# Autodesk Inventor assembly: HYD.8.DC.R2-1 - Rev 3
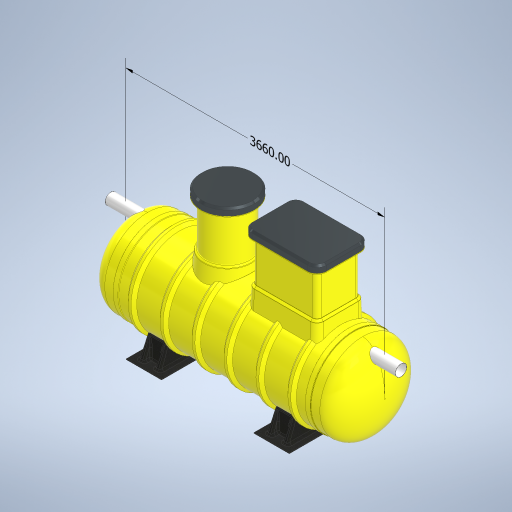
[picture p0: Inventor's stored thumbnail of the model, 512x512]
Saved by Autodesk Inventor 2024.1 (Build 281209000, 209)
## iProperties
Created: 2023-10
Part Number: HYD.8.DC.R2-1 - Rev 3
Document SubType Name: Assembly
Designer: macga
Author: macga
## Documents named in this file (43)
- D:\$ Protector Vault\Workspace\Automation Files\1. Protector Stardard Products\HydroProtectors\FAMILY\HYD.8 -Vernon\HYD.8.DC.R2-1 - Rev 3.iam
- D:\$ Protector Vault\Workspace\1. Protector Stardard Products\HydroProtectors\FAMILY\HORIZONTAL TANK - IPART\HORIZONTAL TANK - IPART.ipt
- D:\$ Protector Vault\Workspace\1. Protector Stardard Products\HydroProtectors\FAMILY\DOME - IPART\DOME - IPART.ipt
- D:\$ Protector Vault\Workspace\1. Protector Stardard Products\HydroProtectors\FAMILY\ACDTUBE - IPART\ACDTUBE - IPART.ipt
- D:\$ Protector Vault\Workspace\1. Protector Stardard Products\HydroProtectors\FAMILY\ACD FLOAT VALVE - IPART\ACD.FloatValve - IASSY\ACD.FVALVE.225.ASSY.iam
- D:\$ Protector Vault\Workspace\1. Protector Stardard Products\HydroProtectors\FAMILY\ACD FLOAT VALVE - IPART\ACD.FloatValve - IASSY.iam
- D:\$ Protector Vault\Workspace\1. Protector Stardard Products\HydroProtectors\FAMILY\ACDTUBE - IPART\ACDTUBE - IPART\ACDTUBE.225-1680.ipt
- D:\$ Protector Vault\Workspace\1. Protector Stardard Products\HydroProtectors\FAMILY\SU.600Dia Manway Adaptor - IPART\SU.MWA.HS.6R - IPART.ipt
- D:\$ Protector Vault\Workspace\1. Protector Stardard Products\HydroProtectors\FAMILY\600x900mm Manway Adaptor - IPART\600x900mm Manway Adaptor - IPART.ipt
- D:\$ Protector Vault\Workspace\1. Protector Stardard Products\HydroProtectors\Coalescer Guide Rail.ipt
- D:\$ Protector Vault\Workspace\1. Protector Stardard Products\Standard Components\600mm Riser.ipt
- D:\$ Protector Vault\Workspace\1. Protector Stardard Products\Standard Components\600x900 - 600mm Manway Riser.ipt
- D:\$ Protector Vault\Workspace\1. Protector Stardard Products\Standard Components\Flanged Vent.ipt
- D:\$ Protector Vault\Workspace\1. Protector Stardard Products\HydroProtectors\Upper Guide Rai Braket.ipt
- D:\$ Protector Vault\Workspace\1. Protector Stardard Products\Xtremeprotector\Vault\Lifting Eye.ipt
- D:\$ Protector Vault\Workspace\1. Protector Stardard Products\Xtremeprotector\Vault\Chain.ipt
- D:\$ Protector Vault\Workspace\1. Protector Stardard Products\Standard Components\600mm Cast Iron Cover ST\600mm Cass D Cover-01.ipt
- D:\$ Protector Vault\Workspace\1. Protector Stardard Products\Standard Components\600mm Cast Iron Cover ST.ipt
- D:\$ Protector Vault\Workspace\Automation Files\600x900mm Manway Cover ST B and D\600x900mm Manway Cover-D.ipt
- D:\$ Protector Vault\Workspace\Automation Files\600x900mm Manway Cover ST B and D.ipt
- D:\$ Protector Vault\Workspace\1. Protector Stardard Products\HydroProtectors\FAMILY\OUTLET ELBOW - IPART\OUTLET ELBOW - IPART.ipt
- D:\$ Protector Vault\Workspace\1. Protector Stardard Products\HydroProtectors\FAMILY\INLET PIPE ELBOW- IPART\INLET PIPE ELBOW- IPART.ipt
- D:\$ Protector Vault\Workspace\1. Protector Stardard Products\HydroProtectors\HYD Oil Probe\Oil Probe Assembly.iam
- D:\$ Protector Vault\Workspace\1. Protector Stardard Products\HydroProtectors\FAMILY\FOOT - IPART\FRP Foot - IPART.ipt
- D:\$ Protector Vault\Workspace\1. Protector Stardard Products\HydroProtectors\FAMILY\HYD.BAFFLE - IPART\SU.BAFFLE.1200\SU.BAFFLE.1200.ipt
- D:\$ Protector Vault\Workspace\1. Protector Stardard Products\HydroProtectors\FAMILY\HYD.BAFFLE - IPART\SU.BAFFLE.1200.ipt
- D:\$ Protector Vault\Workspace\1. Protector Stardard Products\HydroProtectors\FAMILY\ACD Base - IPART\SU.ACDBASE.1200\SU.ACDBASE.1200.ipt
- D:\$ Protector Vault\Workspace\1. Protector Stardard Products\HydroProtectors\FAMILY\ACD Base - IPART\SU.ACDBASE.1200.ipt
- D:\$ Protector Vault\Workspace\1. Protector Stardard Products\HydroProtectors\FAMILY\CF.BASE - IPART\CF BASE SINGLE - IPART\SU.CFBASE.1200\SU.CFBASE.1200.ipt
- D:\$ Protector Vault\Workspace\1. Protector Stardard Products\HydroProtectors\FAMILY\CF.BASE - IPART\CF BASE SINGLE - IPART\SU.CFBASE.1200.ipt
- D:\$ Protector Vault\Workspace\1. Protector Stardard Products\HydroProtectors\FAMILY\SU.600Dia Manway Adaptor - IPART\Horizontal 600mmDia Manway Adaptor (FLANGED) SU.MWA.HS.6R-1850-1850\SU.MWA.HS.6R-1200.ipt
- D:\$ Protector Vault\Workspace\1. Protector Stardard Products\HydroProtectors\FAMILY\600x900mm Manway Adaptor - IPART\600x900mm Manway Adaptor - IPART\SU.MRADAPTOR.1200.600Lx900W.ipt
- D:\$ Protector Vault\Workspace\1. Protector Stardard Products\HydroProtectors\FAMILY\ACD Base - IPART\Moulds\Coalescer Guide Rail-015.ipt
- D:\$ Protector Vault\Workspace\1. Protector Stardard Products\HydroProtectors\FAMILY\FOOT - IPART\FRP Foot - IPART\SU.HS.FOOT.1200.ipt
- D:\$ Protector Vault\Workspace\1. Protector Stardard Products\Ecoprotectors\ISO 4065 Pipe DN160x1.3xS63 - 3000.ipt
- D:\$ Protector Vault\Workspace\1. Protector Stardard Products\HydroProtectors\FAMILY\OUTLET ELBOW - IPART\OUTLET ELBOW - IPART\OutletPipeElbow.150D-100DCoupling.ipt
- D:\$ Protector Vault\Workspace\1. Protector Stardard Products\HydroProtectors\FAMILY\INLET PIPE ELBOW- IPART\INLET PIPE ELBOW- IPART\InletPipeElbow.150D.ipt
- D:\$ Protector Vault\Workspace\1. Protector Stardard Products\HydroProtectors\FAMILY\DOME - IPART\DOME - IPART\SU.DOME.1200-7.ipt
- D:\$ Protector Vault\Workspace\1. Protector Stardard Products\HydroProtectors\FAMILY\HORIZONTAL TANK - IPART\HORIZONTAL TANK - IPART\WIN.HB.1200x2780L-7.ipt
- D:\$ Protector Vault\Workspace\1. Protector Stardard Products\HydroProtectors\FAMILY\COALESCER FILTER - IPART\CF-R2.iam
- D:\$ Protector Vault\Workspace\1. Protector Stardard Products\Xtremeprotector\Vault\Chain\Chain-29.ipt
- D:\$ Protector Vault\Workspace\1. Protector Stardard Products\Horizontal Storage Tanks\ISO 4065 Pipe DN160x1.3xS63 - 1000.ipt
- D:\$ Protector Vault\Workspace\1. Protector Stardard Products\Trade Waste Sampling Point Assembly 150.iam
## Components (30 placed, 26 different names)
1. WIN.HB.1200x2780L-7:1
2. SU.DOME.1200-7:1 — Mate:3, Mate:4, Angle:7, Flush:1, Flush:59, Tangent:4
3. SU.DOME.1200-7:2 — Mate:1, Mate:5, Angle:8
4. SU.BAFFLE.1200:1 — Flush:1
5. SU.ACDBASE.1200:1
6. ACDTUBE.225-1680:1 — Angle:11, Mate:11, Flush:2, Mate:22
7. ACD.FVALVE.225.ASSY:1 [sub-assembly] — Mate:11, Flush:2
8. SU.CFBASE.1200:1
9. SU.MWA.HS.6R-1200:1 — Mate:22, Angle:13, Mate:23, Mate:33, Mate:34, Mate:35, Mate:58, Flush:57
10. SU.MRADAPTOR.1200.600Lx900W:1 — Mate:24, Mate:30, Mate:31, Mate:32, Mate:36, Mate:37, Flush:58
11. CF-R2:1 [sub-assembly] — Mate:26
12. Coalescer Guide Rail-015:1 — Mate:38, Mate:39, Flush:23
13. 600mm Riser:1 — Flush:22, Mate:33, Mate:44, Mate:45
14. 600x900 - 600mm Manway Riser:1
15. Flanged Vent:1 — Mate:34, Mate:35
16. Flanged Vent:2 — Mate:36, Mate:37
17. Upper Guide Rai Braket:1 — Mate:38, Mate:39, Flush:23
18. Lifting Eye:1 — Mate:40, Mate:41, Mate:42, Tangent:3
19. Chain-29:1 — Tangent:3
20. 600mm Cass D Cover-01:1 — Mate:44, Mate:45
21. 600x900mm Manway Cover-D:1 — Mate:46, Flush:24, Flush:25
22. ISO 4065 Pipe DN160x1.3xS63 - 3000:1 — Mate:47
23. OutletPipeElbow.150D-100DCoupling:1 — Mate:51
24. InletPipeElbow.150D:1 — Mate:55, Mate:67, Mate:68
25. Oil Probe Assembly:1 [sub-assembly] — Mate:58, Flush:57, Angle:17
26. SU.HS.FOOT.1200:1 — Mate:59, Mate:60, Angle:15
27. SU.HS.FOOT.1200:2 — Mate:61, Mate:62, Angle:16
28. ISO 4065 Pipe DN160x1.3xS63 - 1000:1 — Mate:69, Mate:70
29. ISO 4065 Pipe DN160x1.3xS63 - 3000:3 — Flush:59, Mate:67, Mate:68, Tangent:4
30. Trade Waste Sampling Point Assembly 150:1 [sub-assembly] — Mate:69, Mate:70
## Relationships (55: Mate 37, Flush 9, Angle 7, Tangent 2)
- Mate:1: SU.DOME.1200-7:2
- Mate:3: SU.DOME.1200-7:1
- Mate:4: SU.DOME.1200-7:1
- Mate:5: SU.DOME.1200-7:2
- Angle:7: SU.DOME.1200-7:1
- Angle:8: SU.DOME.1200-7:2
- Flush:1: SU.DOME.1200-7:1 ↔ SU.BAFFLE.1200:1
- Angle:11: ACDTUBE.225-1680:1
- Mate:11: ACDTUBE.225-1680:1 ↔ ACD.FVALVE.225.ASSY:1
- Flush:2: ACDTUBE.225-1680:1 ↔ ACD.FVALVE.225.ASSY:1
- Mate:22: ACDTUBE.225-1680:1 ↔ SU.MWA.HS.6R-1200:1
- Angle:13: SU.MWA.HS.6R-1200:1
- Mate:23: SU.MWA.HS.6R-1200:1
- Mate:24: SU.MRADAPTOR.1200.600Lx900W:1
- Mate:26: CF-R2:1
- Mate:30: SU.MRADAPTOR.1200.600Lx900W:1
- Mate:31: SU.MRADAPTOR.1200.600Lx900W:1
- Mate:32: SU.MRADAPTOR.1200.600Lx900W:1
- Flush:22: 600mm Riser:1
- Mate:33: SU.MWA.HS.6R-1200:1 ↔ 600mm Riser:1
- Mate:34: SU.MWA.HS.6R-1200:1 ↔ Flanged Vent:1
- Mate:35: SU.MWA.HS.6R-1200:1 ↔ Flanged Vent:1
- Mate:36: SU.MRADAPTOR.1200.600Lx900W:1 ↔ Flanged Vent:2
- Mate:37: SU.MRADAPTOR.1200.600Lx900W:1 ↔ Flanged Vent:2
- Mate:38: Coalescer Guide Rail-015:1 ↔ Upper Guide Rai Braket:1
- Mate:39: Coalescer Guide Rail-015:1 ↔ Upper Guide Rai Braket:1
- Flush:23: Coalescer Guide Rail-015:1 ↔ Upper Guide Rai Braket:1
- Mate:40: Lifting Eye:1
- Mate:41: Lifting Eye:1
- Mate:42: Lifting Eye:1
- Tangent:3: Lifting Eye:1 ↔ Chain-29:1
- Mate:44: 600mm Riser:1 ↔ 600mm Cass D Cover-01:1
- Mate:45: 600mm Riser:1 ↔ 600mm Cass D Cover-01:1
- Mate:46: 600x900mm Manway Cover-D:1
- Flush:24: 600x900mm Manway Cover-D:1
- Flush:25: 600x900mm Manway Cover-D:1
- Mate:47: ISO 4065 Pipe DN160x1.3xS63 - 3000:1
- Mate:51: OutletPipeElbow.150D-100DCoupling:1
- Mate:55: InletPipeElbow.150D:1
- Mate:58: SU.MWA.HS.6R-1200:1 ↔ Oil Probe Assembly:1
- Flush:57: SU.MWA.HS.6R-1200:1 ↔ Oil Probe Assembly:1
- Mate:59: SU.HS.FOOT.1200:1
- Mate:60: SU.HS.FOOT.1200:1
- Mate:61: SU.HS.FOOT.1200:2
- Mate:62: SU.HS.FOOT.1200:2
- Angle:15: SU.HS.FOOT.1200:1
- Angle:16: SU.HS.FOOT.1200:2
- Angle:17: Oil Probe Assembly:1
- Flush:58: SU.MRADAPTOR.1200.600Lx900W:1
- Flush:59: SU.DOME.1200-7:1 ↔ ISO 4065 Pipe DN160x1.3xS63 - 3000:3
- Mate:67: InletPipeElbow.150D:1 ↔ ISO 4065 Pipe DN160x1.3xS63 - 3000:3
- Mate:68: InletPipeElbow.150D:1 ↔ ISO 4065 Pipe DN160x1.3xS63 - 3000:3
- Tangent:4: SU.DOME.1200-7:1 ↔ ISO 4065 Pipe DN160x1.3xS63 - 3000:3
- Mate:69: ISO 4065 Pipe DN160x1.3xS63 - 1000:1 ↔ Trade Waste Sampling Point Assembly 150:1
- Mate:70: ISO 4065 Pipe DN160x1.3xS63 - 1000:1 ↔ Trade Waste Sampling Point Assembly 150:1
